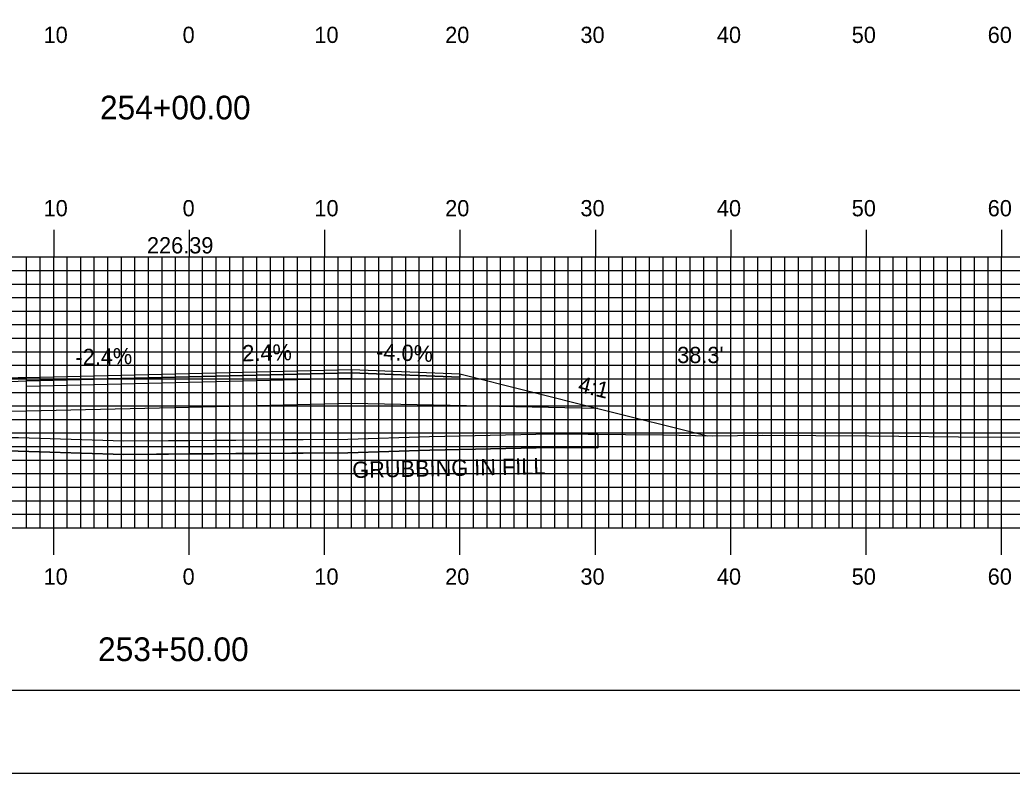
# Model space of a CAD drawing. Extents: x 1804684 to 1805027, y 442591 to 442811.
# Drawn here: x 1804837.2 to 1804910.5, y 442590.5 to 442646.2 of the extents above; entities that cross this region are included whole.
import ezdxf

# ---------------------------------------------------------------- set-up
doc = ezdxf.new("R2010")
doc.units = 0
for name, color, linetype in [('ANNOTATION', 7, 'Continuous'), ('BORDER', 7, 'Continuous'), ('D_Roadway_Centerline', 7, 'Continuous'), ('D_Roadway_Centerline_Text', 7, 'Continuous'), ('D_Roadway_Edge_Shoulder', 7, 'Continuous'), ('D_Roadway_Edge_TW', 7, 'Continuous'), ('D_Roadway_Pavement', 7, 'Continuous'), ('D_Roadway_SlopeLines', 7, 'Continuous'), ('D_Roadway_SubGrade', 7, 'Continuous'), ('D_Text_Standard', 7, 'Continuous'), ('GRUBBING IN FILL', 7, 'Continuous'), ('H_V ANNOTATION', 7, 'Continuous'), ('MAJOR', 7, 'Continuous'), ('MINOR', 7, 'Continuous'), ('PLOT BOUNDARY', 7, 'Continuous'), ('S_Roadway_Centerline', 7, 'Continuous')]:
    doc.layers.add(name, color=color, linetype=linetype)

msp = doc.modelspace()

# ---------------------------------------------------------------- linework, layer by layer
at = {"layer": 'BORDER'}
msp.add_lwpolyline([(1804700.08, 442596.665), (1805020.08, 442596.665), (1805020.08, 442806.665), (1804700.08, 442806.665)], close=True, dxfattribs=at)
at = {"layer": 'D_Roadway_Centerline'}
msp.add_lwpolyline([(1804811.617, 442614.934), (1804817.68, 442616.45), (1804819.506, 442616.906), (1804829.68, 442619.45), (1804837.68, 442619.77), (1804849.68, 442620.058), (1804861.68, 442620.346), (1804869.68, 442620.026), (1804879.854, 442617.482), (1804887.962, 442615.455)], dxfattribs=at)
at = {"layer": 'D_Roadway_Edge_Shoulder'}
for points in [[(1804861.68, 442620.346), (1804869.68, 442620.026), (1804869.68, 442619.776), (1804861.68, 442620.096)], [(1804837.68, 442619.77), (1804829.68, 442619.45), (1804829.68, 442619.2), (1804837.68, 442619.52)]]:
    msp.add_lwpolyline(points, close=True, dxfattribs=at)
at = {"layer": 'D_Roadway_Edge_TW'}
msp.add_lwpolyline([(1804837.68, 442619.52), (1804837.68, 442619.77), (1804849.68, 442620.058), (1804861.68, 442620.346), (1804861.68, 442620.096), (1804849.68, 442619.808)], close=True, dxfattribs=at)
at = {"layer": 'D_Roadway_Pavement'}
msp.add_lwpolyline([(1804837.68, 442619.103), (1804837.68, 442619.52), (1804849.68, 442619.808), (1804861.68, 442620.096), (1804861.68, 442619.679), (1804849.68, 442619.391)], close=True, dxfattribs=at)
at = {"layer": 'D_Roadway_SlopeLines'}
msp.add_lwpolyline([(1804869.68, 442620.026), (1804879.854, 442617.482), (1804887.962, 442615.455)], dxfattribs=at)
at = {"layer": 'D_Roadway_SubGrade'}
msp.add_lwpolyline([(1804837.68, 442617.27), (1804819.506, 442616.906), (1804829.68, 442619.45), (1804829.68, 442619.2), (1804837.68, 442619.52), (1804849.68, 442619.808), (1804861.68, 442620.096), (1804869.68, 442619.776), (1804869.68, 442620.026), (1804879.854, 442617.482), (1804861.68, 442617.846), (1804849.68, 442617.558)], close=True, dxfattribs=at)
at = {"layer": 'GRUBBING IN FILL'}
msp.add_line((1804879.854, 442615.569), (1804879.854, 442614.569), dxfattribs=at)
msp.add_line((1804879.854, 442615.569), (1804879.854, 442614.569), dxfattribs=at)
for points in [[(1804819.506, 442614.929), (1804820.406, 442614.989), (1804824.925, 442615.172), (1804829.444, 442615.354), (1804833.261, 442615.337), (1804837.078, 442615.321), (1804840.97, 442615.2), (1804844.863, 442615.079), (1804849.68, 442615.118), (1804849.68, 442614.118), (1804844.852, 442614.079), (1804840.956, 442614.2), (1804837.06, 442614.321), (1804833.261, 442614.337), (1804829.462, 442614.354), (1804824.961, 442614.172), (1804819.506, 442613.927)], [(1804819.506, 442614.929), (1804820.406, 442614.989), (1804824.925, 442615.172), (1804829.444, 442615.354), (1804833.261, 442615.337), (1804837.078, 442615.321), (1804840.97, 442615.2), (1804844.863, 442615.079), (1804849.68, 442615.118), (1804849.68, 442614.118), (1804844.852, 442614.079), (1804840.956, 442614.2), (1804837.06, 442614.321), (1804833.261, 442614.337), (1804829.462, 442614.354), (1804824.961, 442614.172), (1804819.506, 442613.927)], [(1804849.68, 442615.118), (1804853.126, 442615.145), (1804856.572, 442615.173), (1804861.389, 442615.211), (1804867.421, 442615.402), (1804871.921, 442615.499), (1804876.422, 442615.595), (1804879.854, 442615.569), (1804879.854, 442614.569), (1804876.429, 442614.595), (1804871.938, 442614.499), (1804867.447, 442614.403), (1804864.428, 442614.307), (1804861.409, 442614.212), (1804853.13, 442614.145), (1804849.68, 442614.118)], [(1804849.68, 442615.118), (1804853.126, 442615.145), (1804856.572, 442615.173), (1804861.389, 442615.211), (1804867.421, 442615.402), (1804871.921, 442615.499), (1804876.422, 442615.595), (1804879.854, 442615.569), (1804879.854, 442614.569), (1804876.429, 442614.595), (1804871.938, 442614.499), (1804867.447, 442614.403), (1804864.428, 442614.307), (1804861.409, 442614.212), (1804853.13, 442614.145), (1804849.68, 442614.118)]]:
    msp.add_lwpolyline(points, close=True, dxfattribs=at)
msp.add_lwpolyline([(1804819.506, 442613.927), (1804820.46, 442613.991), (1804829.462, 442614.354), (1804837.06, 442614.321), (1804844.852, 442614.079), (1804861.409, 442614.212), (1804867.447, 442614.403), (1804876.429, 442614.595), (1804879.854, 442614.569)], dxfattribs=at)
msp.add_lwpolyline([(1804819.506, 442613.927), (1804820.46, 442613.991), (1804829.462, 442614.354), (1804837.06, 442614.321), (1804844.852, 442614.079), (1804861.409, 442614.212), (1804867.447, 442614.403), (1804876.429, 442614.595), (1804879.854, 442614.569)], dxfattribs=at)
at = {"layer": 'MAJOR'}
for p, q in [((1804839.68, 442630.669), (1804839.68, 442628.665)), ((1804849.68, 442630.669), (1804849.68, 442628.665)), ((1804859.68, 442630.669), (1804859.68, 442628.665)), ((1804869.68, 442630.669), (1804869.68, 442628.665)), ((1804879.68, 442630.669), (1804879.68, 442628.665)), ((1804889.68, 442630.669), (1804889.68, 442628.665)), ((1804899.68, 442630.669), (1804899.68, 442628.665)), ((1804909.68, 442630.669), (1804909.68, 442628.665)), ((1804709.68, 442628.665), (1804989.68, 442628.665)), ((1804709.68, 442628.665), (1804989.68, 442628.665)), ((1804839.68, 442608.665), (1804839.68, 442628.665)), ((1804849.68, 442608.665), (1804849.68, 442628.665)), ((1804859.68, 442608.665), (1804859.68, 442628.665)), ((1804869.68, 442608.665), (1804869.68, 442628.665)), ((1804879.68, 442608.665), (1804879.68, 442628.665)), ((1804889.68, 442608.665), (1804889.68, 442628.665)), ((1804899.68, 442608.665), (1804899.68, 442628.665)), ((1804909.68, 442608.665), (1804909.68, 442628.665)), ((1804709.68, 442623.665), (1804989.68, 442623.665)), ((1804709.68, 442618.665), (1804989.68, 442618.665)), ((1804709.68, 442613.665), (1804989.68, 442613.665)), ((1804709.68, 442608.665), (1804989.68, 442608.665)), ((1804709.68, 442608.665), (1804989.68, 442608.665)), ((1804839.68, 442606.661), (1804839.68, 442608.665)), ((1804849.68, 442606.661), (1804849.68, 442608.665)), ((1804859.68, 442606.661), (1804859.68, 442608.665)), ((1804869.68, 442606.661), (1804869.68, 442608.665)), ((1804879.68, 442606.661), (1804879.68, 442608.665)), ((1804889.68, 442606.661), (1804889.68, 442608.665)), ((1804899.68, 442606.661), (1804899.68, 442608.665)), ((1804909.68, 442606.661), (1804909.68, 442608.665))]:
    msp.add_line(p, q, dxfattribs=at)
at = {"layer": 'MINOR'}
for p, q in [((1804837.68, 442608.665), (1804837.68, 442628.665)), ((1804838.68, 442608.665), (1804838.68, 442628.665)), ((1804840.68, 442608.665), (1804840.68, 442628.665)), ((1804841.68, 442608.665), (1804841.68, 442628.665)), ((1804842.68, 442608.665), (1804842.68, 442628.665)), ((1804843.68, 442608.665), (1804843.68, 442628.665)), ((1804844.68, 442608.665), (1804844.68, 442628.665)), ((1804845.68, 442608.665), (1804845.68, 442628.665)), ((1804846.68, 442608.665), (1804846.68, 442628.665)), ((1804847.68, 442608.665), (1804847.68, 442628.665)), ((1804848.68, 442608.665), (1804848.68, 442628.665)), ((1804850.68, 442608.665), (1804850.68, 442628.665)), ((1804851.68, 442608.665), (1804851.68, 442628.665)), ((1804852.68, 442608.665), (1804852.68, 442628.665)), ((1804853.68, 442608.665), (1804853.68, 442628.665)), ((1804854.68, 442608.665), (1804854.68, 442628.665)), ((1804855.68, 442608.665), (1804855.68, 442628.665)), ((1804856.68, 442608.665), (1804856.68, 442628.665)), ((1804857.68, 442608.665), (1804857.68, 442628.665)), ((1804858.68, 442608.665), (1804858.68, 442628.665)), ((1804860.68, 442608.665), (1804860.68, 442628.665)), ((1804861.68, 442608.665), (1804861.68, 442628.665)), ((1804862.68, 442608.665), (1804862.68, 442628.665)), ((1804863.68, 442608.665), (1804863.68, 442628.665)), ((1804864.68, 442608.665), (1804864.68, 442628.665)), ((1804865.68, 442608.665), (1804865.68, 442628.665)), ((1804866.68, 442608.665), (1804866.68, 442628.665)), ((1804867.68, 442608.665), (1804867.68, 442628.665)), ((1804868.68, 442608.665), (1804868.68, 442628.665)), ((1804870.68, 442608.665), (1804870.68, 442628.665)), ((1804871.68, 442608.665), (1804871.68, 442628.665)), ((1804872.68, 442608.665), (1804872.68, 442628.665)), ((1804873.68, 442608.665), (1804873.68, 442628.665)), ((1804874.68, 442608.665), (1804874.68, 442628.665)), ((1804875.68, 442608.665), (1804875.68, 442628.665)), ((1804876.68, 442608.665), (1804876.68, 442628.665)), ((1804877.68, 442608.665), (1804877.68, 442628.665)), ((1804878.68, 442608.665), (1804878.68, 442628.665)), ((1804880.68, 442608.665), (1804880.68, 442628.665)), ((1804881.68, 442608.665), (1804881.68, 442628.665)), ((1804882.68, 442608.665), (1804882.68, 442628.665)), ((1804883.68, 442608.665), (1804883.68, 442628.665)), ((1804884.68, 442608.665), (1804884.68, 442628.665)), ((1804885.68, 442608.665), (1804885.68, 442628.665)), ((1804886.68, 442608.665), (1804886.68, 442628.665)), ((1804887.68, 442608.665), (1804887.68, 442628.665)), ((1804888.68, 442608.665), (1804888.68, 442628.665)), ((1804890.68, 442608.665), (1804890.68, 442628.665)), ((1804891.68, 442608.665), (1804891.68, 442628.665)), ((1804892.68, 442608.665), (1804892.68, 442628.665)), ((1804893.68, 442608.665), (1804893.68, 442628.665)), ((1804894.68, 442608.665), (1804894.68, 442628.665)), ((1804895.68, 442608.665), (1804895.68, 442628.665)), ((1804896.68, 442608.665), (1804896.68, 442628.665)), ((1804897.68, 442608.665), (1804897.68, 442628.665)), ((1804898.68, 442608.665), (1804898.68, 442628.665)), ((1804900.68, 442608.665), (1804900.68, 442628.665)), ((1804901.68, 442608.665), (1804901.68, 442628.665)), ((1804902.68, 442608.665), (1804902.68, 442628.665)), ((1804903.68, 442608.665), (1804903.68, 442628.665)), ((1804904.68, 442608.665), (1804904.68, 442628.665)), ((1804905.68, 442608.665), (1804905.68, 442628.665)), ((1804906.68, 442608.665), (1804906.68, 442628.665)), ((1804907.68, 442608.665), (1804907.68, 442628.665)), ((1804908.68, 442608.665), (1804908.68, 442628.665)), ((1804709.68, 442627.665), (1804989.68, 442627.665)), ((1804709.68, 442626.665), (1804989.68, 442626.665)), ((1804709.68, 442625.665), (1804989.68, 442625.665)), ((1804709.68, 442624.665), (1804989.68, 442624.665)), ((1804709.68, 442622.665), (1804989.68, 442622.665)), ((1804709.68, 442621.665), (1804989.68, 442621.665)), ((1804709.68, 442620.665), (1804989.68, 442620.665)), ((1804709.68, 442619.665), (1804989.68, 442619.665)), ((1804709.68, 442617.665), (1804989.68, 442617.665)), ((1804709.68, 442616.665), (1804989.68, 442616.665)), ((1804709.68, 442615.665), (1804989.68, 442615.665)), ((1804709.68, 442614.665), (1804989.68, 442614.665)), ((1804709.68, 442612.665), (1804989.68, 442612.665)), ((1804709.68, 442611.665), (1804989.68, 442611.665)), ((1804709.68, 442610.665), (1804989.68, 442610.665)), ((1804709.68, 442609.665), (1804989.68, 442609.665))]:
    msp.add_line(p, q, dxfattribs=at)
at = {"layer": 'PLOT BOUNDARY'}
msp.add_lwpolyline([(1804683.894, 442590.547), (1805023.894, 442590.547), (1805023.894, 442810.547), (1804683.894, 442810.547)], close=True, dxfattribs=at)
at = {"layer": 'S_Roadway_Centerline'}
msp.add_lwpolyline([(1804783.042, 442614.738), (1804791.17, 442614.815), (1804795.425, 442614.923), (1804799.516, 442615.02), (1804816.79, 442614.897), (1804818.393, 442614.855), (1804820.406, 442614.989), (1804829.444, 442615.354), (1804837.078, 442615.321), (1804844.863, 442615.079), (1804861.389, 442615.211), (1804867.421, 442615.402), (1804876.422, 442615.595), (1804884.646, 442615.534), (1804888.297, 442615.447), (1804892.042, 442615.497), (1804899.877, 442615.446), (1804908.7, 442615.36), (1804914.143, 442615.376)], dxfattribs=at)

# ---------------------------------------------------------------- texts
at = {"layer": 'ANNOTATION'}
for s, rotation, p in [('-2.4%', 1.37483, (1804841.3, 442620.657)), ('2.4%', 1.37483, (1804853.621, 442620.953)), ('-4.0%', 357.70939, (1804863.472, 442621.076)), ('4:1', 345.96376, (1804878.327, 442618.726))]:
    msp.add_text(s, height=1.2, rotation=rotation, dxfattribs=at).set_placement(p)
at = {"layer": 'D_Roadway_Centerline'}
for s, p in [('C', (1804849.675, 442620.058)), ('L', (1804849.68, 442620.051))]:
    msp.add_text(s, height=0.0146, dxfattribs=at).set_placement(p)
at = {"layer": 'D_Roadway_Centerline_Text'}
msp.add_text('226.39', height=1.2, dxfattribs=at).set_placement((1804846.566, 442628.924))
at = {"layer": 'D_Text_Standard'}
msp.add_text("38.3'", height=1.2, dxfattribs=at).set_placement((1804885.721, 442620.827))
at = {"layer": 'GRUBBING IN FILL'}
msp.add_text('GRUBBING IN FILL', height=1.2, rotation=1.16831, dxfattribs=at).set_placement((1804861.74, 442612.339))
at = {"layer": 'H_V ANNOTATION'}
for s, height, p in [('10', 1.2, (1804838.931, 442644.465)), ('0', 1.2, (1804849.198, 442644.465)), ('10', 1.2, (1804858.931, 442644.465)), ('20', 1.2, (1804868.588, 442644.465)), ('30', 1.2, (1804878.578, 442644.465)), ('40', 1.2, (1804888.653, 442644.465)), ('50', 1.2, (1804898.61, 442644.465)), ('60', 1.2, (1804908.653, 442644.465)), ('254+00.00', 1.75, (1804843.094, 442638.821)), ('10', 1.2, (1804838.931, 442631.665)), ('0', 1.2, (1804849.198, 442631.665)), ('10', 1.2, (1804858.931, 442631.665)), ('20', 1.2, (1804868.588, 442631.665)), ('30', 1.2, (1804878.578, 442631.665)), ('40', 1.2, (1804888.653, 442631.665)), ('50', 1.2, (1804898.61, 442631.665)), ('60', 1.2, (1804908.653, 442631.665)), ('10', 1.2, (1804838.931, 442604.465)), ('0', 1.2, (1804849.198, 442604.465)), ('10', 1.2, (1804858.931, 442604.465)), ('20', 1.2, (1804868.588, 442604.465)), ('30', 1.2, (1804878.578, 442604.465)), ('40', 1.2, (1804888.653, 442604.465)), ('50', 1.2, (1804898.61, 442604.465)), ('60', 1.2, (1804908.653, 442604.465)), ('253+50.00', 1.75, (1804842.954, 442598.821))]:
    msp.add_text(s, height=height, dxfattribs=at).set_placement(p)

doc.saveas('drawing.dxf')
